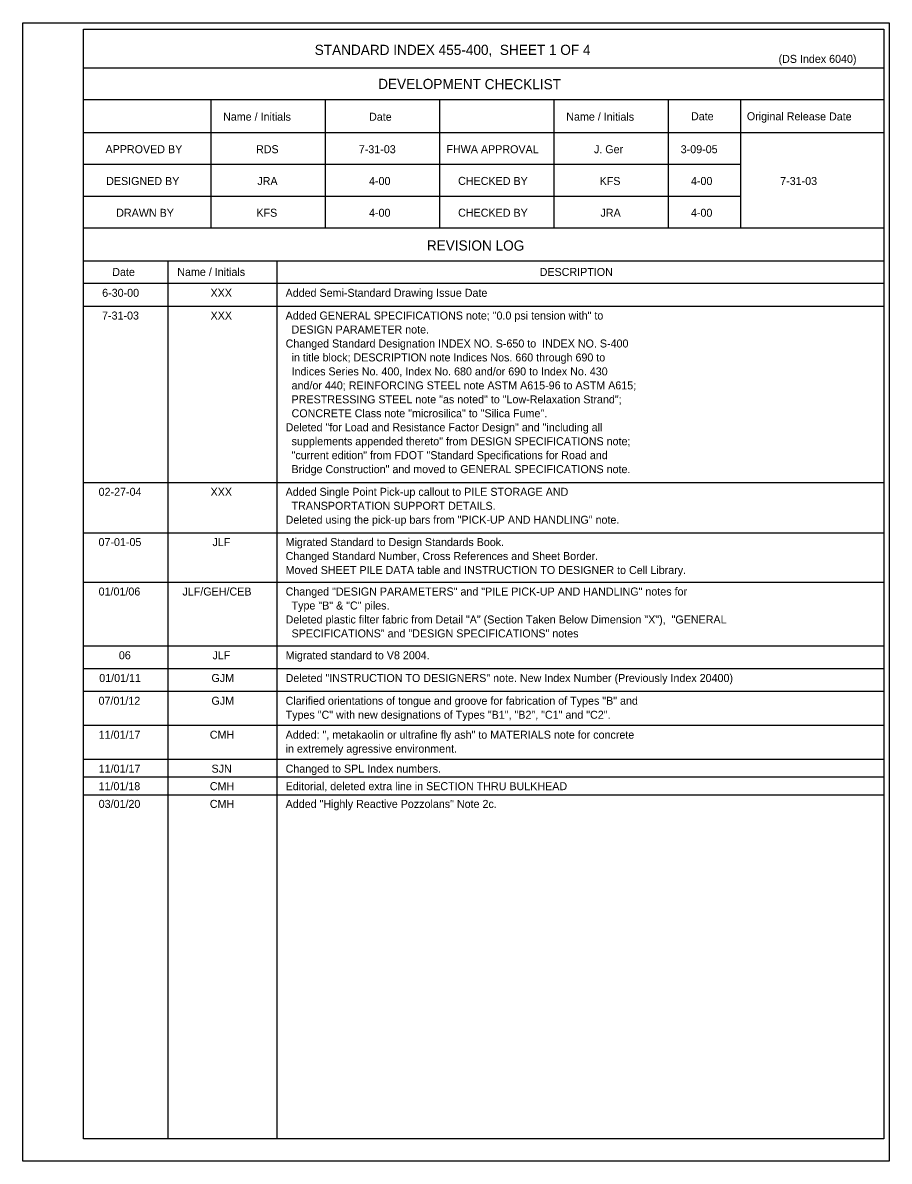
# Model space of a CAD drawing. Extents: x 111162.5 to 111216.6, y 110741.1 to 110776.1.
# Drawn here: x 111200.27 to 111216.63, y 110752.75 to 110774.25 of the extents above; entities that cross this region are included whole.
import ezdxf

# ---------------------------------------------------------------- set-up
doc = ezdxf.new("R2010")
doc.units = 0
for name, color, linetype in [('Border', 7, 'Continuous'), ('Patterning', 7, 'Continuous'), ('SheetBorder_dp', 7, 'Continuous'), ('SheetLines_dp', 7, 'Continuous')]:
    doc.layers.add(name, color=color, linetype=linetype)

msp = doc.modelspace()

# ---------------------------------------------------------------- linework, layer by layer
at = {"layer": 'Border'}
for p, q in [((111216.53, 110773.391), (111201.42, 110773.391)), ((111216.53, 110772.791), (111201.42, 110772.791)), ((111203.82, 110772.791), (111203.82, 110770.37)), ((111205.98, 110772.791), (111205.98, 110770.37)), ((111208.14, 110772.791), (111208.14, 110770.37)), ((111210.3, 110772.791), (111210.3, 110770.37)), ((111212.46, 110772.791), (111212.46, 110770.37)), ((111213.821, 110772.791), (111213.821, 110770.37)), ((111216.53, 110772.17), (111201.42, 110772.17)), ((111213.821, 110771.57), (111201.42, 110771.57)), ((111213.821, 110770.97), (111201.42, 110770.97)), ((111216.53, 110770.37), (111201.42, 110770.37)), ((111216.53, 110769.749), (111201.42, 110769.749)), ((111203.01, 110769.749), (111203.01, 110753.17)), ((111205.067, 110769.749), (111205.067, 110753.17)), ((111216.53, 110769.327), (111201.42, 110769.327))]:
    msp.add_line(p, q, dxfattribs=at)
msp.add_lwpolyline([(111201.42, 110774.127), (111216.53, 110774.127), (111216.53, 110753.17), (111201.42, 110753.17)], close=True, dxfattribs=at)
at = {"layer": 'Patterning'}
for p, q in [((111201.42, 110768.897), (111216.53, 110768.897)), ((111201.42, 110765.569), (111216.53, 110765.569)), ((111201.42, 110764.619), (111216.53, 110764.619)), ((111201.42, 110763.685), (111216.53, 110763.685)), ((111201.42, 110762.481), (111216.53, 110762.481)), ((111201.42, 110762.052), (111216.53, 110762.052)), ((111201.42, 110761.623), (111216.53, 110761.623)), ((111201.42, 110760.981), (111216.53, 110760.981)), ((111201.42, 110760.34), (111216.53, 110760.34)), ((111201.42, 110760.005), (111216.53, 110760.005)), ((111201.42, 110759.669), (111216.53, 110759.669))]:
    msp.add_line(p, q, dxfattribs=at)
at = {"layer": 'SheetLines_dp'}
msp.add_line((111200.272, 110752.749), (111200.272, 110752.749), dxfattribs=at)
msp.add_lwpolyline([(111200.272, 110774.249), (111216.632, 110774.249), (111216.632, 110752.749), (111200.272, 110752.749)], close=True, dxfattribs=at)

# ---------------------------------------------------------------- texts
at = {"layer": 'SheetBorder_dp'}
for s, height, p in [('STANDARD INDEX 455-400,  SHEET 1 OF 4', 0.192, (111205.784, 110773.641)), ('(DS Index 6040)', 0.1512, (111214.542, 110773.491)), ('RDS', 0.1512, (111204.676, 110771.785)), ('7-31-03', 0.1512, (111206.617, 110771.785)), ('J. Ger', 0.1512, (111211.057, 110771.785)), ('3-09-05', 0.1512, (111212.695, 110771.785)), ('JRA', 0.1512, (111204.701, 110771.185)), ('4-00', 0.1512, (111206.81, 110771.185)), ('KFS', 0.1512, (111211.164, 110771.185)), ('4-00', 0.1512, (111212.888, 110771.185)), ('7-31-03', 0.1512, (111214.573, 110771.185)), ('KFS', 0.1512, (111204.684, 110770.585)), ('4-00', 0.1512, (111206.81, 110770.585)), ('JRA', 0.1512, (111211.181, 110770.585)), ('4-00', 0.1512, (111212.888, 110770.585)), ('DESCRIPTION', 0.1512, (111210.032, 110769.467)), ('6-30-00', 0.1512, (111201.771, 110769.073)), ('XXX', 0.1512, (111203.817, 110769.073)), ('Added Semi-Standard Drawing Issue Date', 0.1512, (111205.234, 110769.073)), ('7-31-03', 0.1512, (111201.769, 110768.644)), ('XXX', 0.1512, (111203.818, 110768.644)), ('Added GENERAL SPECIFICATIONS note; "0.0 psi tension with" to', 0.1512, (111205.235, 110768.644)), ('  DESIGN PARAMETER note.', 0.1512, (111205.235, 110768.38)), ('Changed Standard Designation INDEX NO. S-650 to  INDEX NO. S-400', 0.1512, (111205.235, 110768.116)), ('  in title block; DESCRIPTION note Indices Nos. 660 through 690 to ', 0.1512, (111205.235, 110767.853)), ('  Indices Series No. 400, Index No. 680 and/or 690 to Index No. 430 ', 0.1512, (111205.235, 110767.589)), ('  and/or 440; REINFORCING STEEL note ASTM A615-96 to ASTM A615;', 0.1512, (111205.235, 110767.325)), ('  PRESTRESSING STEEL note "as noted" to "Low-Relaxation Strand";', 0.1512, (111205.235, 110767.061)), ('  CONCRETE Class note "microsilica" to "Silica Fume".', 0.1512, (111205.235, 110766.798)), ('Deleted "for Load and Resistance Factor Design" and "including all ', 0.1512, (111205.235, 110766.534)), ('  supplements appended thereto" from DESIGN SPECIFICATIONS note;', 0.1512, (111205.235, 110766.27)), ('  "current edition" from FDOT "Standard Specifications for Road and', 0.1512, (111205.235, 110766.007)), ('  Bridge Construction" and moved to GENERAL SPECIFICATIONS note.', 0.1512, (111205.235, 110765.743)), ('02-27-04', 0.1512, (111201.704, 110765.315)), ('XXX', 0.1512, (111203.818, 110765.315)), ('Added Single Point Pick-up callout to PILE STORAGE AND ', 0.1512, (111205.235, 110765.315)), ('  TRANSPORTATION SUPPORT DETAILS.', 0.1512, (111205.235, 110765.051)), ('Deleted using the pick-up bars from "PICK-UP AND HANDLING" note.', 0.1512, (111205.235, 110764.788)), ('07-01-05', 0.1512, (111201.702, 110764.366)), ('JLF', 0.1512, (111203.855, 110764.366)), ('Migrated Standard to Design Standards Book.', 0.1512, (111205.235, 110764.366)), ('Changed Standard Number, Cross References and Sheet Border.', 0.1512, (111205.235, 110764.102)), ('Moved SHEET PILE DATA table and INSTRUCTION TO DESIGNER to Cell Library.', 0.1512, (111205.235, 110763.838)), ('01/01/06', 0.1512, (111201.704, 110763.432)), ('JLF/GEH/CEB', 0.1512, (111203.287, 110763.432)), ('Changed "DESIGN PARAMETERS" and "PILE PICK-UP AND HANDLING" notes for ', 0.1512, (111205.235, 110763.432)), ('  Type "B" & "C" piles.', 0.1512, (111205.235, 110763.168)), ('Deleted plastic filter fabric from Detail "A" (Section Taken Below Dimension "X"),  "GENERAL ', 0.1512, (111205.235, 110762.904)), ('  SPECIFICATIONS" and "DESIGN SPECIFICATIONS" notes', 0.1512, (111205.235, 110762.641)), ('06', 0.1512, (111202.086, 110762.228)), ('JLF', 0.1512, (111203.855, 110762.228)), ('Migrated standard to V8 2004.', 0.1512, (111205.235, 110762.228)), ('01/01/11', 0.1512, (111201.716, 110761.799)), ('GJM', 0.1512, (111203.835, 110761.799)), ('Deleted "INSTRUCTION TO DESIGNERS" note. New Index Number (Previously Index 20400)', 0.1512, (111205.235, 110761.799)), ('07/01/12', 0.1512, (111201.703, 110761.369)), ('GJM', 0.1512, (111203.835, 110761.369)), ('Clarified orientations of tongue and groove for fabrication of Types "B" and', 0.1512, (111205.235, 110761.369)), ('Types "C" with new designations of Types "B1", "B2", "C1" and "C2".', 0.1512, (111205.235, 110761.105)), ('11/01/17', 0.1512, (111201.706, 110760.728)), ('CMH', 0.1512, (111203.804, 110760.728)), ('Added: ", metakaolin or ultrafine fly ash" to MATERIALS note for concrete', 0.1512, (111205.235, 110760.728)), ('in extremely agressive environment.', 0.1512, (111205.235, 110760.464)), ('11/01/17', 0.1512, (111201.706, 110760.087)), ('SJN', 0.1512, (111203.836, 110760.087)), ('Changed to SPL Index numbers.', 0.1512, (111205.235, 110760.087)), ('11/01/18', 0.1512, (111201.703, 110759.756)), ('CMH', 0.1512, (111203.804, 110759.756)), ('Editorial, deleted extra line in SECTION THRU BULKHEAD', 0.1512, (111205.235, 110759.756)), ('03/01/20', 0.1512, (111201.705, 110759.421)), ('CMH', 0.1512, (111203.804, 110759.421)), ('Added "Highly Reactive Pozzolans" Note 2c.', 0.1512, (111205.235, 110759.421))]:
    msp.add_text(s, height=height, dxfattribs=at).set_placement(p)
for s, height, p in [('DEVELOPMENT CHECKLIST', 0.192, (111206.982, 110772.999)), ('Name / Initials', 0.1512, (111204.054, 110772.401)), ('Date', 0.1512, (111206.81, 110772.399)), ('Name / Initials', 0.1512, (111210.534, 110772.401)), ('Date', 0.1512, (111212.889, 110772.408)), ('Original Release Date', 0.1512, (111213.944, 110772.408)), ('APPROVED BY', 0.1512, (111201.834, 110771.787)), ('FHWA APPROVAL', 0.1512, (111208.271, 110771.787)), ('DESIGNED BY', 0.1512, (111201.846, 110771.186)), ('CHECKED BY', 0.1512, (111208.492, 110771.187)), ('DRAWN BY', 0.1512, (111202.036, 110770.586)), ('CHECKED BY', 0.1512, (111208.492, 110770.587)), ('REVISION LOG', 0.192, (111207.901, 110769.949)), ('Date', 0.1512, (111201.962, 110769.467)), ('Name / Initials', 0.1512, (111203.189, 110769.469))]:
    msp.add_text(s, height=height, rotation=359.8756, dxfattribs=at).set_placement(p)

doc.saveas('drawing.dxf')
